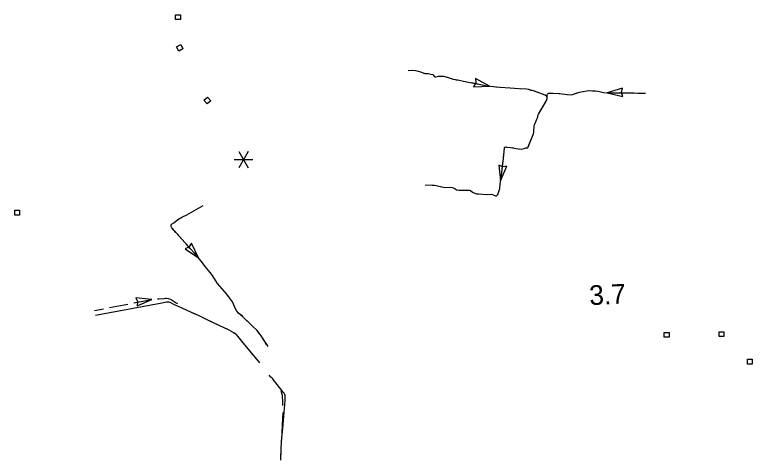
# Model space of a CAD drawing. Extents: x -160 to 6143532, y -375 to 762199.
# Drawn here: x -138.69 to -105.91, y -313.76 to -293.96 of the extents above; entities that cross this region are included whole.
import ezdxf

# ---------------------------------------------------------------- set-up
doc = ezdxf.new("R2010")
doc.units = 0
for name, color, linetype in [('Level 43', 7, 'Continuous'), ('Level 48', 7, 'Continuous'), ('Level 56', 7, 'Continuous')]:
    doc.layers.add(name, color=color, linetype=linetype)

msp = doc.modelspace()

# ---------------------------------------------------------------- linework, layer by layer
at = {"layer": 'Level 43'}
for p, q in [((-118.202, -296.992), (-118.293, -297.158)), ((-117.584, -297.142), (-118.206, -296.801)), ((-118.206, -296.801), (-118.202, -296.99)), ((-118.293, -297.158), (-117.584, -297.142)), ((-111.675, -297.227), (-112.354, -297.434)), ((-111.718, -297.411), (-111.675, -297.227)), ((-112.354, -297.434), (-111.663, -297.595)), ((-111.663, -297.595), (-111.718, -297.414)), ((-117.005, -300.715), (-117.178, -300.641)), ((-117.178, -300.641), (-117.093, -301.346)), ((-117.093, -301.346), (-116.815, -300.693)), ((-116.815, -300.693), (-117.002, -300.716)), ((-130.831, -304.118), (-130.939, -304.273)), ((-130.528, -304.759), (-130.831, -304.118)), ((-130.94, -304.275), (-131.111, -304.356)), ((-131.111, -304.356), (-130.528, -304.759)), ((-132.598, -306.611), (-133.304, -306.534)), ((-133.304, -306.534), (-133.228, -306.707)), ((-133.248, -306.897), (-132.598, -306.611)), ((-133.227, -306.709), (-133.248, -306.897))]:
    msp.add_line(p, q, dxfattribs=at)
for points in [[(-120.444, -301.523), (-120.139, -301.535), (-119.96, -301.546), (-119.773, -301.589), (-119.633, -301.624), (-119.528, -301.636), (-119.318, -301.624), (-119.248, -301.636), (-119.197, -301.647), (-119.135, -301.682), (-119.049, -301.737), (-118.937, -301.76), (-118.855, -301.76), (-118.656, -301.76), (-118.477, -301.76), (-118.438, -301.768), (-118.345, -301.838), (-118.287, -301.877), (-118.166, -301.92), (-118.065, -301.92), (-117.715, -301.951), (-117.493, -301.939), (-117.43, -301.959), (-117.318, -302.002), (-117.28, -302.003), (-117.247, -301.977), (-117.223, -301.942), (-117.167, -301.81), (-117.132, -301.68), (-117.112, -301.479), (-117.06, -301.113), (-116.952, -300.203), (-116.924, -299.882), (-116.919, -299.864), (-116.9, -299.849), (-116.882, -299.84), (-116.862, -299.836), (-116.818, -299.839), (-116.658, -299.853), (-116.315, -299.917), (-116.171, -299.929), (-116.11, -299.924), (-116.048, -299.91), (-116.007, -299.895), (-115.974, -299.869), (-115.88, -299.869), (-115.68, -299.363), (-115.637, -299.254), (-115.614, -299.186), (-115.61, -299.126), (-115.602, -298.925), (-115.594, -298.855), (-115.439, -298.504), (-115.433, -298.434), (-115.415, -298.386), (-115.067, -297.796), (-115.032, -297.73), (-115.02, -297.689), (-115.02, -297.644), (-115.034, -297.601), (-115.053, -297.583), (-115.114, -297.54), (-115.626, -297.345), (-115.686, -297.328), (-115.746, -297.324), (-115.797, -297.299), (-115.845, -297.285), (-115.947, -297.275), (-116.289, -297.25), (-116.674, -297.223), (-117.13, -297.188), (-117.408, -297.164), (-117.684, -297.129), (-118.749, -296.921), (-118.988, -296.87), (-119.105, -296.859), (-119.185, -296.839), (-119.562, -296.722), (-119.632, -296.707), (-119.679, -296.701), (-119.733, -296.703), (-119.868, -296.711), (-119.973, -296.742), (-120, -296.736), (-120.06, -296.668), (-120.097, -296.637), (-120.191, -296.619), (-120.321, -296.59), (-120.448, -296.58), (-120.64, -296.518), (-120.882, -296.454), (-121.006, -296.436), (-121.207, -296.45)], [(-120.745, -296.49), (-120.882, -296.454), (-121.006, -296.436), (-121.207, -296.45)], [(-119.719, -296.702), (-119.733, -296.703), (-119.868, -296.711), (-119.973, -296.742), (-120, -296.736), (-120.06, -296.668), (-120.097, -296.637), (-120.191, -296.619), (-120.321, -296.59), (-120.448, -296.58), (-120.484, -296.569)], [(-119.059, -296.863), (-119.105, -296.859), (-119.185, -296.839), (-119.453, -296.756)], [(-118.656, -296.939), (-118.749, -296.921), (-118.988, -296.87), (-119.059, -296.863)], [(-117.584, -297.142), (-117.684, -297.129), (-118.389, -296.992)], [(-116.496, -297.235), (-116.674, -297.223), (-117.13, -297.188), (-117.312, -297.172)], [(-115.43, -297.42), (-115.626, -297.345), (-115.686, -297.328), (-115.746, -297.324), (-115.797, -297.299), (-115.845, -297.285), (-115.947, -297.275), (-116.223, -297.255)], [(-115.294, -298.18), (-115.067, -297.796), (-115.032, -297.73), (-115.02, -297.689), (-115.02, -297.644), (-115.034, -297.601), (-115.053, -297.583), (-115.114, -297.54), (-115.174, -297.517)], [(-115.02, -297.644), (-115.02, -297.523), (-115.015, -297.493), (-114.995, -297.47), (-114.981, -297.458), (-114.968, -297.451), (-114.943, -297.451), (-114.851, -297.443), (-114.454, -297.46), (-114.133, -297.505), (-113.936, -297.515), (-113.893, -297.499), (-113.813, -297.468), (-113.583, -297.398), (-113.42, -297.365), (-113.266, -297.343), (-113.157, -297.334), (-113.013, -297.336), (-112.877, -297.345), (-112.772, -297.359), (-112.638, -297.38), (-112.577, -297.404), (-112.513, -297.421), (-112.314, -297.437), (-112.108, -297.427), (-111.511, -297.425), (-111.159, -297.431), (-110.999, -297.441), (-110.859, -297.451), (-110.659, -297.449)], [(-115.02, -297.644), (-115.02, -297.523), (-115.015, -297.493), (-114.995, -297.47), (-114.981, -297.458), (-114.968, -297.451), (-114.943, -297.451), (-114.851, -297.443), (-114.774, -297.446)], [(-114.501, -297.458), (-114.454, -297.46), (-114.133, -297.505), (-113.936, -297.515), (-113.893, -297.499), (-113.813, -297.468), (-113.699, -297.433)], [(-113.434, -297.368), (-113.42, -297.365), (-113.266, -297.343), (-113.157, -297.334), (-113.013, -297.336), (-112.877, -297.345), (-112.772, -297.359), (-112.638, -297.38), (-112.622, -297.387)], [(-112.354, -297.434), (-112.314, -297.437), (-112.108, -297.427), (-111.536, -297.425)], [(-111.263, -297.429), (-111.159, -297.431), (-110.999, -297.441), (-110.859, -297.451), (-110.659, -297.449)], [(-115.619, -299.201), (-115.614, -299.186), (-115.61, -299.126), (-115.602, -298.925), (-115.594, -298.855), (-115.439, -298.504), (-115.433, -298.434), (-115.427, -298.418)], [(-115.868, -299.837), (-115.717, -299.456)], [(-116.959, -300.262), (-116.952, -300.203), (-116.924, -299.882), (-116.919, -299.864), (-116.9, -299.849), (-116.882, -299.84), (-116.862, -299.836), (-116.818, -299.839), (-116.658, -299.853), (-116.512, -299.88)], [(-116.242, -299.923), (-116.171, -299.929), (-116.11, -299.924), (-116.048, -299.91), (-116.007, -299.895), (-115.974, -299.869), (-115.88, -299.869), (-115.868, -299.837)], [(-117.093, -301.346), (-117.06, -301.113), (-116.991, -300.533)], [(-120.444, -301.523), (-120.139, -301.535), (-120.034, -301.541)], [(-119.767, -301.591), (-119.633, -301.624), (-119.528, -301.636), (-119.318, -301.624), (-119.248, -301.636), (-119.197, -301.647), (-119.135, -301.682), (-119.049, -301.737), (-118.981, -301.751)], [(-118.709, -301.76), (-118.656, -301.76), (-118.477, -301.76), (-118.438, -301.768), (-118.345, -301.838), (-118.287, -301.877), (-118.166, -301.92), (-118.065, -301.92), (-117.934, -301.932)], [(-117.662, -301.948), (-117.493, -301.939), (-117.43, -301.959), (-117.318, -302.002), (-117.28, -302.003), (-117.247, -301.977), (-117.223, -301.942), (-117.167, -301.81), (-117.132, -301.68), (-117.126, -301.617)], [(-127.43, -308.704), (-127.468, -308.633), (-127.572, -308.481), (-127.73, -308.231), (-127.912, -307.996), (-128.141, -307.787), (-128.545, -307.386), (-128.745, -307.225), (-128.816, -307.139), (-128.884, -307.034), (-128.92, -306.927), (-129.018, -306.721), (-129.149, -306.546), (-129.265, -306.382), (-129.682, -305.906), (-129.896, -305.552), (-130.006, -305.421), (-130.232, -305.141), (-130.393, -304.921), (-130.699, -304.554), (-130.887, -304.352), (-131.708, -303.429), (-131.743, -303.373), (-131.743, -303.328), (-131.743, -303.304), (-131.722, -303.272), (-131.624, -303.203), (-131.44, -303.066), (-131.264, -302.962), (-131.041, -302.849), (-130.315, -302.444)], [(-131.524, -303.636), (-131.705, -303.433)], [(-131.251, -303.942), (-131.524, -303.636)], [(-130.678, -304.579), (-130.699, -304.554), (-130.887, -304.352), (-131.07, -304.146)], [(-129.855, -305.619), (-129.896, -305.552), (-130.006, -305.421), (-130.232, -305.141), (-130.356, -304.971)], [(-135.107, -307.304), (-134.864, -307.263), (-132.232, -306.771), (-132.002, -306.73), (-131.946, -306.719), (-131.914, -306.715), (-131.875, -306.715), (-131.847, -306.722), (-131.792, -306.736), (-131.572, -306.844), (-131.427, -306.91), (-130.851, -307.184), (-130.541, -307.305), (-130.032, -307.562), (-129.167, -307.964), (-128.962, -308.074), (-128.896, -308.118), (-128.857, -308.155), (-128.783, -308.242), (-128.618, -308.465), (-127.812, -309.434)], [(-134.476, -306.967), (-133.671, -306.816)], [(-133.403, -306.762), (-132.598, -306.611)], [(-132.344, -306.582), (-132.286, -306.579), (-132.053, -306.566), (-131.992, -306.562), (-131.941, -306.561), (-131.863, -306.571), (-131.814, -306.59), (-131.741, -306.618), (-131.519, -306.762), (-131.463, -306.797)], [(-128.574, -307.362), (-128.745, -307.225), (-128.816, -307.139), (-128.884, -307.034), (-128.92, -306.927), (-129.018, -306.721), (-129.032, -306.703)], [(-135.142, -307.099), (-134.9, -307.058), (-134.742, -307.029)], [(-131.262, -306.988), (-130.851, -307.184), (-130.696, -307.244)], [(-130.017, -307.569), (-129.53, -307.795)], [(-127.805, -308.134), (-127.912, -307.996), (-128.141, -307.787), (-128.378, -307.552)], [(-129.282, -307.91), (-129.167, -307.964), (-128.962, -308.074), (-128.921, -308.101)], [(-128.921, -308.101), (-128.896, -308.118), (-128.857, -308.155), (-128.783, -308.242), (-128.657, -308.412)], [(-127.502, -308.638), (-127.574, -308.478), (-127.649, -308.359)], [(-128.485, -308.624), (-127.962, -309.254)], [(-126.87, -313.757), (-126.867, -313.718), (-126.85, -313.295), (-126.826, -312.926), (-126.766, -312.164), (-126.665, -311.105), (-126.664, -310.939), (-126.673, -310.88), (-126.687, -310.829), (-126.711, -310.782), (-126.759, -310.728), (-126.86, -310.594), (-127.089, -310.314), (-127.155, -310.231), (-127.22, -310.136), (-127.256, -310.1), (-127.3, -310.067), (-127.378, -309.978)], [(-127.213, -310.146), (-127.22, -310.136), (-127.256, -310.1), (-127.3, -310.067), (-127.378, -309.978)], [(-126.962, -310.47), (-127.089, -310.314), (-127.155, -310.231), (-127.213, -310.146)], [(-126.771, -311.323), (-126.771, -311.123), (-126.786, -310.939), (-126.794, -310.88), (-126.809, -310.829), (-126.849, -310.669)], [(-126.797, -312.551), (-126.785, -312.186), (-126.766, -311.64)], [(-126.864, -313.641), (-126.85, -313.295), (-126.826, -312.926), (-126.818, -312.823)]]:
    msp.add_lwpolyline(points, dxfattribs=at)
at = {"layer": 'Level 48'}
for p, q in [((-128.314, -300.041), (-128.728, -300.758)), ((-128.728, -300.041), (-128.314, -300.758)), ((-128.935, -300.399), (-128.108, -300.399))]:
    msp.add_line(p, q, dxfattribs=at)
at = {"layer": 'Level 56'}
for points in [[(-131.544, -294.177), (-131.544, -293.961), (-131.328, -293.961), (-131.328, -294.177)], [(-131.311, -295.289), (-131.212, -295.48), (-131.404, -295.579), (-131.503, -295.388)], [(-130.122, -297.619), (-129.979, -297.781), (-130.141, -297.923), (-130.284, -297.762)], [(-138.69, -302.862), (-138.69, -302.646), (-138.474, -302.646), (-138.474, -302.862)], [(-109.82, -308.295), (-109.82, -308.08), (-109.604, -308.08), (-109.604, -308.295)], [(-107.385, -308.261), (-107.385, -308.046), (-107.169, -308.046), (-107.169, -308.261)], [(-106.124, -309.482), (-106.124, -309.267), (-105.908, -309.267), (-105.908, -309.482)]]:
    msp.add_lwpolyline(points, close=True, dxfattribs=at)

# ---------------------------------------------------------------- texts
at = {"layer": 'Level 48'}
msp.add_text('3.7', height=0.8737, rotation=2.758, dxfattribs=at).set_placement((-113.132, -306.866))

doc.saveas('drawing.dxf')
